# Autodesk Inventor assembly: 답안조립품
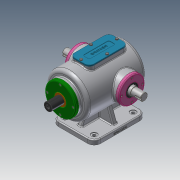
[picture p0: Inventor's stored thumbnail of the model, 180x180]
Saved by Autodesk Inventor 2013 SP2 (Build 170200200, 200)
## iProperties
Created: 2021-11
Part Number: 답안조립품
Document SubType Name: Assembly
Designer: aa
Author: aa
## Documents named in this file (14)
- C:\Users\aa\Desktop\711106V1018\답안조립품.iam
- C:\Users\aa\Desktop\711106V1018\본체.ipt
- C:\Users\aa\Desktop\711106V1018\베어링 6205.ipt
- 베어링 6205.ipt
- C:\Users\aa\Desktop\711106V1018\볼트 M4x0.7.ipt
- C:\Users\aa\Desktop\711106V1018\부시.ipt
- C:\Users\aa\Desktop\711106V1018\상부커버.ipt
- C:\Users\aa\Desktop\711106V1018\슬라이드 커버.ipt
- C:\Users\aa\Desktop\711106V1018\슬라이드.ipt
- C:\Users\aa\Desktop\711106V1018\오일실.ipt
- 오일실.ipt
- C:\Users\aa\Desktop\711106V1018\육각머리볼트 M4.ipt
- C:\Users\aa\Desktop\711106V1018\축 커버.ipt
- C:\Users\aa\Desktop\711106V1018\편심축.ipt
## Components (12 placed, 1 different names)
1. M4x0.7:1
2. M4x0.7:2
3. M4x0.7:3
4. M4x0.7:4
5. M4x0.7:5
6. M4x0.7:6
7. M4x0.7:7
8. M4x0.7:8
9. M4x0.7:9
10. M4x0.7:10
11. M4x0.7:11
12. M4x0.7:12
